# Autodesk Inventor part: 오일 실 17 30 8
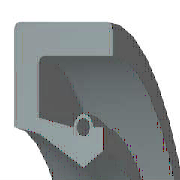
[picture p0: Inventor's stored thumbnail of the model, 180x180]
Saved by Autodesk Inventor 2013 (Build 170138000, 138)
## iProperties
Created: 2012-02
Part Number: 오일 실 17 30 8
Material: 고무
Description: 오일-실
Document SubType Name: Modeling
Standard: KS B 2804
Designer: mduedu
Standards Organization: KS
Language: ko-KR
Size Designation: S - 17 30 8
Categories: <MemberInstance><Categories><Category DisplayName="샤프트 부품" InternalName="7f7aeb1f-a693-4053-b835-cee3144e0d98" Mnemonic="SHFT"><Category DisplayName="실링" Intern
Density: 0.93 g/cm^3
Mass: 1.6913 g
Surface Area: 28.0102 cm^2
Volume: 1.81861 cm^3
IsCustomPart: 1
Author: mduedu
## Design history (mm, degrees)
revolve "본체" stored, may be unused: angle "d17" = 90 deg
revolve "스프링1" stored, may be unused: angle "d18" = 90 deg
body "Solid1"
sketch "스케치1"
  geometry: L1 (0, 15)-(8, 15); L2 (8, 15)-(8, 13.75); L3 (8, 13.75)-(1.75, 13.75); L4 (0, 15)-(0, 10.6); L5 (0, 10.6)-(1.75, 10.25); L6 (1.75, 10.25)-(4.9, 8.5); L7 (4.9, 8.5)-(0, 8.5); L8 (6.3, 9.375)-(6.3, 10.6); L9 (0, 0)-(9.586, 0) reference; L10 (4.9, 8.5)-(6.3, 9.375); L11 (0, 18)-(0, -3) reference; L12 (-1.917, 0)-(11.503, 0) reference; L13 (4.2, 10.6)-(1.75, 11.09); L14 (1.75, 11.09)-(1.75, 13.75); L15 (6.3, 10.6)-(5.6, 10.6); C1 r 0.455 at (4.9, 10.6); A1 r 0.7 centre (4.9, 10.6) between (5.6, 10.6) and (4.2, 10.6)
  constraints: 26 end point, 5 horizontal alignment, 4 perpendicular, 2 centre point, 2 collinear, 2 horizontal, 2 parallel, 2 point on circle, 2 point on line, 2 vertical alignment, 1 coincident
  dimensions: "d0" = 30 diameter of L1 L9 (= SD2); "d1" = 18.75 diameter of L8.start L9 (= ABDM); "d2" = 1.25 distance of L1.end L2.end (computed from SD); "d3" = 0.91 diameter of C1 (= SPDI); "d4" = 1.4 diameter of A1 (= SPDA); "d5" = 17 diameter of L6.end L9 (= NND); "d6" = 20.5 diameter of L5.end L9 (= TKDM); "d7" = 21.2 diameter of L4.end L9 (= HLDM); "d8" = 4.9 distance from line of C1.centre L4 (= SPDST); "d9" = 6.3 distance between parallel lines of L8 L4 (= SDI); "d10" = 8 distance between parallel lines of L2 L4 (= SWDT); "d12" = 1.75 distance between parallel lines of L14 L4 (= SD)
fillet "모깎기1" dims "d11" = 0.3 (= RR)
other parameters: "SD2" = 30 [user parameter; used in 1 equation term], "SWDT" = 8 [user parameter; used in 1 equation term], "RR" = 0.3 [user parameter; used in 1 equation term], "SD" = 1.75 [user parameter; used in 2 equation terms], "NND" = 17 [user parameter; used in 1 equation term], "SPDA" = 1.4 [user parameter; used in 1 equation term], "SPDI" = 0.91 [user parameter; used in 1 equation term], "TKDM" = 20.5 [user parameter; used in 1 equation term], "HLDM" = 21.2 [user parameter; used in 1 equation term], "ABDM" = 18.75 [user parameter; used in 1 equation term], "SDI" = 6.3 [user parameter; used in 1 equation term], "SPDST" = 4.9 [user parameter; used in 1 equation term], "d13" = 0, "d14" = 0, "d15" = 0, "LAB" = 0.35 [user parameter]
